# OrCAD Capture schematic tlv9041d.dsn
size A
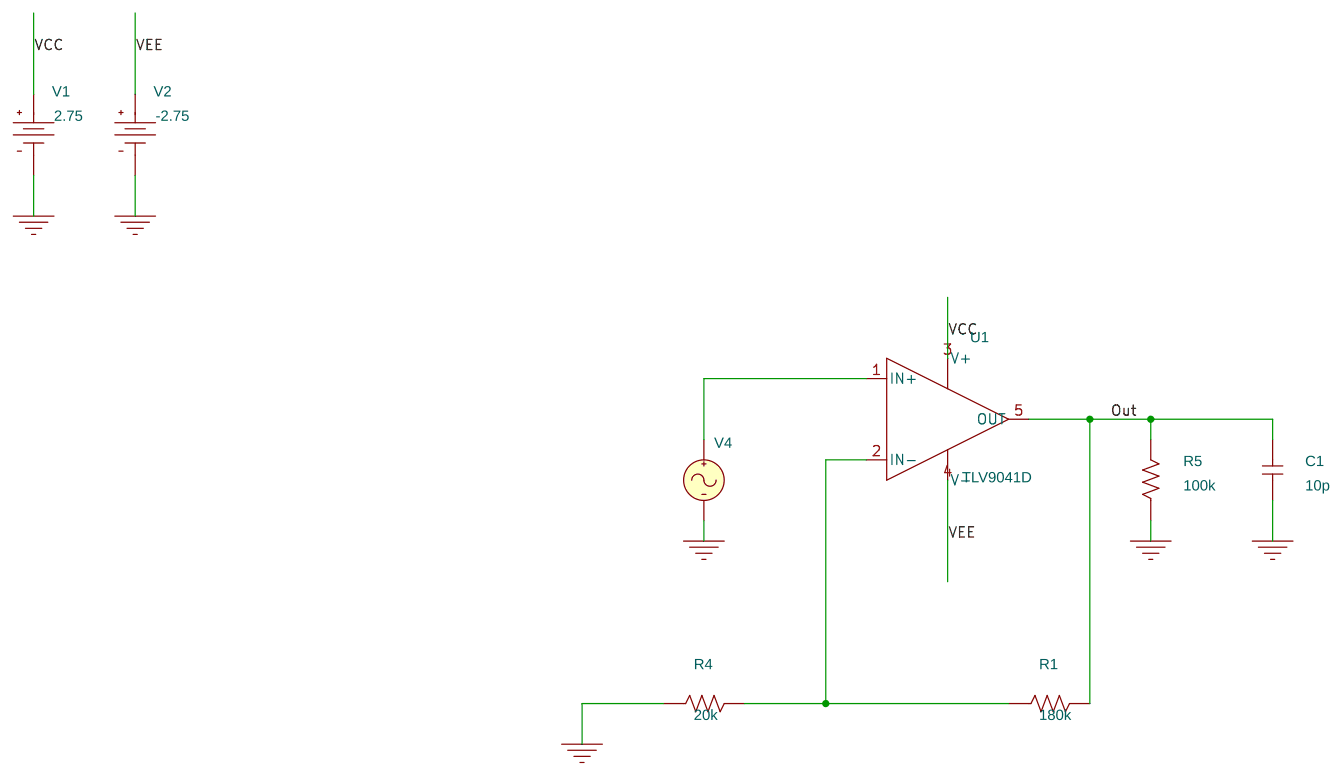
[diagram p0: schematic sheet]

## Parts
C1  10p  [cap196]
R1  180k  [AXRC05]
R4  20k  [AXRC05]
R5  100k  [AXRC05]
U1  TLV9041D
V1  VDC
V2  VDC
V4  VAC

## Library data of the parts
C1 = C
R1 R4 R5 = R
U1 = TLV9041D
V1 = VDC: AppProp: DC$Voltage$0$-1; DC: 2.75
V2 = VDC: AppProp: DC$Voltage$0$-1; DC: -2.75
V4 = VAC

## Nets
VCC: U1.3(V+) V1.0(+)
VEE: U1.4(V-) V2.0(+)
0: C1.1 R4.1 R5.1 V1.1(-) V2.1(-) V4.2(-)
Out: C1.2 R1.2 R5.2 U1.5(OUT)
N03489: U1.1(IN+) V4.1(+)
N04641: R1.1 R4.2 U1.2(IN-)
